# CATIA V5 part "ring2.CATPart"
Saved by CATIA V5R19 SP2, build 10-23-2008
Part number: ring2
Bounding box of the stored display mesh (mm): x 0 to 1653.668, y 0 to 756, z -42.839 to 459.189
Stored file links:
  C:\BEHROOZ\catia learning\tarh haye mashin\hb\ring2.CATPart
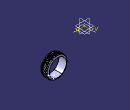
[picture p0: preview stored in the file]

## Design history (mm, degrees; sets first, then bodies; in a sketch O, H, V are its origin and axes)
Body1 (main body)
  Plane1: stored without definition
  DatumSurface1
  DatumCurve1
  Line1: stored without definition
  Sketch1 on Plane1, origin (1402.6545, 0, 0), H (0, 1, 0), V (0, 0, 1)
    point P1 (572, 2.0151)
    construction line L1 (756, 2.0151) -> (572, 2.0151)
    axis line L2 (664, 2.0151) -> (664, -65.0687)
    arc A1 centre (689.6466, 13.5884) radius 67.3551 from (756, 2.0151) to (740.1148, -31.0174) cw
    point P6 (572, 2.0151)
    arc A2 centre (638.3534, 13.5884) radius 67.3551 from (572, 2.0151) to (587.8852, -31.0174) ccw
    line L3 (756, 2.0151) -> (572, 2.0151)
    line L4 (614.1102, -42.8387) -> (713.8898, -42.8387)
    arc A3 centre (713.8898, -7.8387) radius 35 from (713.8898, -42.8387) to (740.1148, -31.0174) ccw
    arc A4 centre (614.1102, -7.8387) radius 35 from (614.1102, -42.8387) to (587.8852, -31.0174) cw
    coincidence: P1 P6
  Shaft1: profile Sketch1, axis Line1, angle 360
  Sketch2 on xy-plane, origin (0, 0, 0), H (1, 0, 0), V (0, 1, 0)
    arc A1 centre (1295.4141, 893.6482) radius 248.3619 from (1484.4905, 732.6086) to (1399.2001, 668.0111) cw
    arc A2 centre (1183.7459, 1041.0878) radius 430.8209 from (1399.2001, 668.0111) to (1484.4905, 732.6086) ccw
    axis line L1 (1429.3512, 665.0609) -> (1358.5547, 665.0609)
    point P9 (1429.3512, 665.0609)
    arc A3 centre (1285.1081, 434.9089) radius 248.3619 from (1474.1844, 595.9485) to (1388.894, 660.546) ccw
    arc A4 centre (1173.4399, 287.4694) radius 430.8209 from (1388.894, 660.546) to (1474.1844, 595.9485) cw
  Plane2: type Offset, RefPlane xy-plane, Offset -61
  Sketch3 on Plane2, origin (0, 0, -61), H (1, 0, 0), V (0, 1, 0)
    projected arc E1 centre (1285.1081, 434.9089) radius 248.3619 from (1474.1844, 595.9485) to (1388.894, 660.546) ccw from Sketch2.A3
    projected arc E2 centre (1173.4399, 287.4694) radius 430.8209 from (1474.1844, 595.9485) to (1388.894, 660.546) ccw from Sketch2.A4
    projected arc E3 centre (1183.7459, 1041.0878) radius 430.8209 from (1399.2001, 668.0111) to (1484.4905, 732.6086) ccw from Sketch2.A2
    projected arc E4 centre (1295.4141, 893.6482) radius 248.3619 from (1399.2001, 668.0111) to (1484.4905, 732.6086) ccw from Sketch2.A1
  Join1: Elements (face of Shaft1 from Sketch1.A1; face of Shaft1 from Sketch1.L4; face of Shaft1 from Sketch1.A4; face of Shaft1 from Sketch1.A3; face of Shaft1 from Sketch1.A2)
  Pocket1: profile Sketch3, direction (0, 0, -1), up to Join1, offset 2
  CircPattern1: of Pocket1, instances 47, angular step 7.6596 {= 360.0*1 deg/CircPattern1.AngularNumber}, axis from face of Shaft1 from Sketch1.A1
